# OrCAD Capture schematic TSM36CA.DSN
size A; title: TSM36CA Bidirectional Surge Protection Device in SOT-23; rev: 1.0; note: Datasheet: SLVSI30
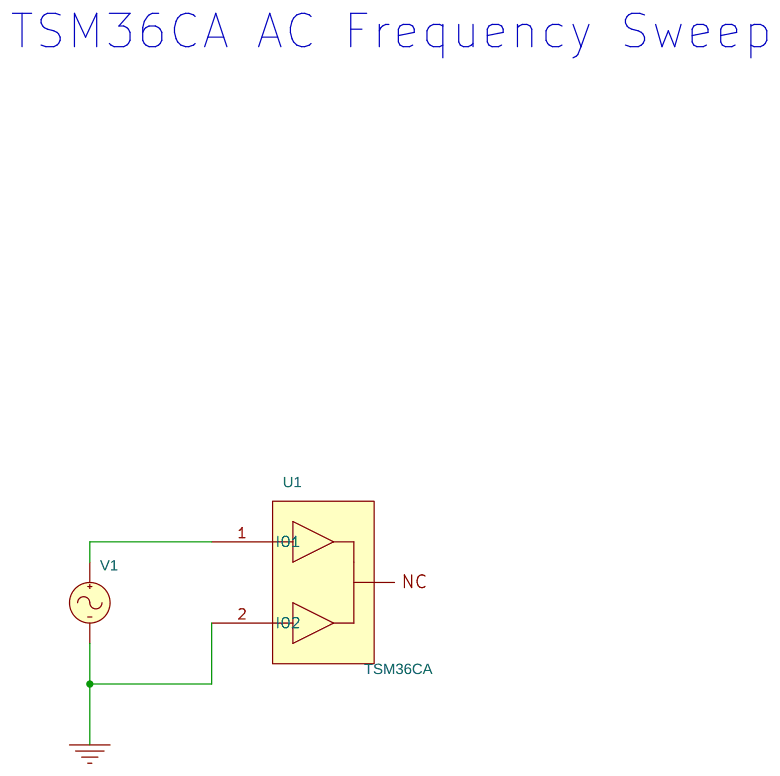
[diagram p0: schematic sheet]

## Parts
U1  TSM36CA
V1  VAC

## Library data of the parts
U1 = TSM36CA
V1 = VAC

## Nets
0: U1.2(IO2) V1.2(-)
N02835: U1.1(IO1) V1.1(+)

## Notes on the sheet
- TSM36CA AC Frequency Sweep
